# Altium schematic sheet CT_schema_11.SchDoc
size 147 x 119 mm
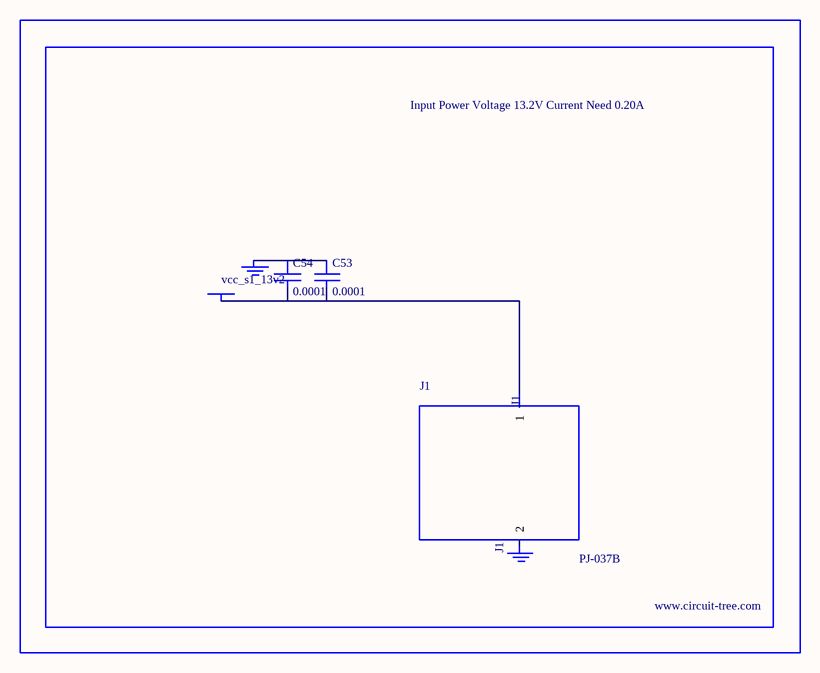
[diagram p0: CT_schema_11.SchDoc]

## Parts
BORDER10  (no value)
C53  0.0001  [EXV-9H]
C54  0.0001  [EXV-9H]
GND_INSTANCE_10_0  (no value)
GND_INSTANCE_10_1  (no value)
J1  PJ-037B  [PJ-037B_PACKAGE]
POWER_INSTANCE_10_0  vcc_s1_13v2

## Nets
NetC53_1: C53.1 C54.1 GND_INSTANCE_10_0.0(GND)
NetC53_2: C53.2 C54.2 J1.1 POWER_INSTANCE_10_0.0(PWR)

Not connected (* = marked no-connect by the designer): GND_INSTANCE_10_1 0(GND); J1 2

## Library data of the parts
BORDER10 = BORDER_PAGE10
C53 C54 = EDK107M035A9HAA
GND_INSTANCE_10_0 GND_INSTANCE_10_1 = GND
POWER_INSTANCE_10_0 = PWR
